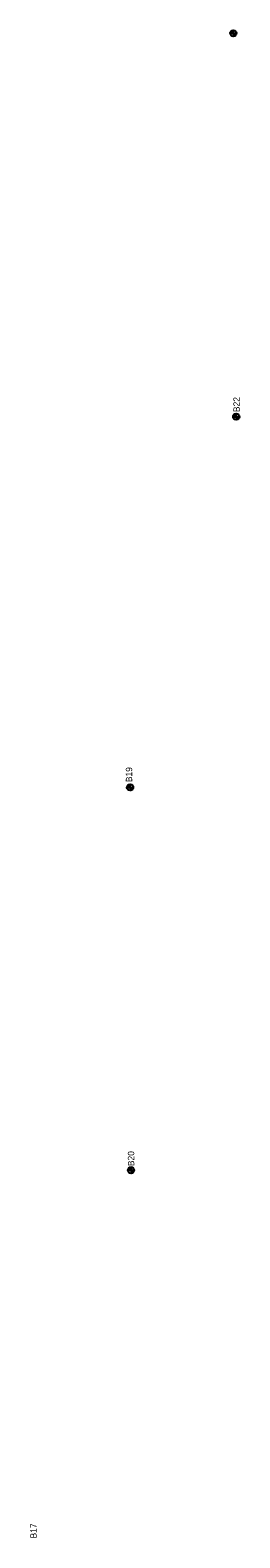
# Model space of a CAD drawing. Extents: x 327762 to 372792, y 127949 to 259367.
# Drawn here: x 361138 to 361467, y 137976 to 140354 of the extents above; entities that cross this region are included whole.
import ezdxf

# ---------------------------------------------------------------- set-up
doc = ezdxf.new("R2010")
doc.units = 0
for name, color, linetype in [('E_SOIL_BORE1 [KAPUR_CADDS_LEVELS]', 7, 'Continuous'), ('E_SOIL_BORE2 [KAPUR_CADDS_LEVELS]', 7, 'Continuous'), ('P_MARK', 7, 'Continuous')]:
    doc.layers.add(name, color=color, linetype=linetype)

msp = doc.modelspace()

# ---------------------------------------------------------------- linework, layer by layer
at = {"layer": 'P_MARK'}
for p, q in [((361452.1, 140348.7), (361462, 140348.7)), ((361457.1, 140353.7), (361457, 140343.7)), ((361456.7, 139744.2), (361466.7, 139744.2)), ((361461.7, 139749.2), (361461.7, 139739.2)), ((361289.9, 139159.7), (361299.9, 139159.7)), ((361294.9, 139164.7), (361294.9, 139154.7)), ((361291.3, 138556.1), (361301.3, 138556.1)), ((361296.3, 138561.1), (361296.3, 138551.1))]:
    msp.add_line(p, q, dxfattribs=at)
for centre in [(361457.1, 140348.7), (361461.7, 139744.2), (361294.9, 139159.7), (361296.3, 138556.1)]:
    msp.add_circle(centre, 5, dxfattribs=at)
for centre, radius, start, end in [((361457.1, 140348.7), 4.5, 89.9869, 179.9869), ((361457.1, 140348.7), 4, 89.9869, 179.9869), ((361457.1, 140348.7), 3.5, 89.9869, 179.9869), ((361457.1, 140348.7), 3, 89.9869, 179.9869), ((361457.1, 140348.7), 2.5, 89.9869, 179.9869), ((361457.1, 140348.7), 2, 89.9869, 179.9869), ((361457.1, 140348.7), 1.5, 89.9869, 179.9869), ((361457.1, 140348.7), 1, 89.9869, 179.9869), ((361457.1, 140348.7), 0.5, 89.9869, 179.9869), ((361457.1, 140348.7), 4.5, 269.9869, 359.9869), ((361457.1, 140348.7), 4, 269.9869, 359.9869), ((361457.1, 140348.7), 3.5, 269.9869, 359.9869), ((361457.1, 140348.7), 3, 269.9869, 359.9869), ((361457.1, 140348.7), 2.5, 269.9869, 359.9869), ((361457.1, 140348.7), 2, 269.9869, 359.9869), ((361457.1, 140348.7), 1.5, 269.9869, 359.9869), ((361457.1, 140348.7), 1, 269.9869, 359.9869), ((361457.1, 140348.7), 0.5, 269.9869, 359.9869), ((361461.7, 139744.2), 4.5, 89.9869, 179.9869), ((361461.7, 139744.2), 4, 89.9869, 179.9869), ((361461.7, 139744.2), 3.5, 89.9869, 179.9869), ((361461.7, 139744.2), 3, 89.9869, 179.9869), ((361461.7, 139744.2), 2.5, 89.9869, 179.9869), ((361461.7, 139744.2), 2, 89.9869, 179.9869), ((361461.7, 139744.2), 1.5, 89.9869, 179.9869), ((361461.7, 139744.2), 1, 89.9869, 179.9869), ((361461.7, 139744.2), 0.5, 89.9869, 179.9869), ((361461.7, 139744.2), 4.5, 269.9869, 359.9869), ((361461.7, 139744.2), 4, 269.9869, 359.9869), ((361461.7, 139744.2), 3.5, 269.9869, 359.9869), ((361461.7, 139744.2), 3, 269.9869, 359.9869), ((361461.7, 139744.2), 2.5, 269.9869, 359.9869), ((361461.7, 139744.2), 2, 269.9869, 359.9869), ((361461.7, 139744.2), 1.5, 269.9869, 359.9869), ((361461.7, 139744.2), 1, 269.9869, 359.9869), ((361461.7, 139744.2), 0.5, 269.9869, 359.9869), ((361294.9, 139159.7), 4.5, 89.9869, 179.9869), ((361294.9, 139159.7), 4, 89.9869, 179.9869), ((361294.9, 139159.7), 3.5, 89.9869, 179.9869), ((361294.9, 139159.7), 3, 89.9869, 179.9869), ((361294.9, 139159.7), 2.5, 89.9869, 179.9869), ((361294.9, 139159.7), 2, 89.9869, 179.9869), ((361294.9, 139159.7), 1.5, 89.9869, 179.9869), ((361294.9, 139159.7), 1, 89.9869, 179.9869), ((361294.9, 139159.7), 0.5, 89.9869, 179.9869), ((361294.9, 139159.7), 4.5, 269.9869, 359.9869), ((361294.9, 139159.7), 4, 269.9869, 359.9869), ((361294.9, 139159.7), 3.5, 269.9869, 359.9869), ((361294.9, 139159.7), 3, 269.9869, 359.9869), ((361294.9, 139159.7), 2.5, 269.9869, 359.9869), ((361294.9, 139159.7), 2, 269.9869, 359.9869), ((361294.9, 139159.7), 1.5, 269.9869, 359.9869), ((361294.9, 139159.7), 1, 269.9869, 359.9869), ((361294.9, 139159.7), 0.5, 269.9869, 359.9869), ((361296.3, 138556.1), 4.5, 89.9869, 179.9869), ((361296.3, 138556.1), 4, 89.9869, 179.9869), ((361296.3, 138556.1), 3.5, 89.9869, 179.9869), ((361296.3, 138556.1), 3, 89.9869, 179.9869), ((361296.3, 138556.1), 2.5, 89.9869, 179.9869), ((361296.3, 138556.1), 2, 89.9869, 179.9869), ((361296.3, 138556.1), 1.5, 89.9869, 179.9869), ((361296.3, 138556.1), 1, 89.9869, 179.9869), ((361296.3, 138556.1), 0.5, 89.9869, 179.9869), ((361296.3, 138556.1), 4.5, 269.9869, 359.9869), ((361296.3, 138556.1), 4, 269.9869, 359.9869), ((361296.3, 138556.1), 3.5, 269.9869, 359.9869), ((361296.3, 138556.1), 3, 269.9869, 359.9869), ((361296.3, 138556.1), 2.5, 269.9869, 359.9869), ((361296.3, 138556.1), 2, 269.9869, 359.9869), ((361296.3, 138556.1), 1.5, 269.9869, 359.9869), ((361296.3, 138556.1), 1, 269.9869, 359.9869), ((361296.3, 138556.1), 0.5, 269.9869, 359.9869)]:
    msp.add_arc(centre, radius, start, end, dxfattribs=at)

# ---------------------------------------------------------------- texts
at = {"layer": 'E_SOIL_BORE1 [KAPUR_CADDS_LEVELS]'}
for s, p in [('B20', (361301.3, 138562.4)), ('B17', (361147.9, 137975.3))]:
    msp.add_text(s, height=10, rotation=89.9869, dxfattribs=at).set_placement(p)
at = {"layer": 'E_SOIL_BORE2 [KAPUR_CADDS_LEVELS]'}
for s, p in [('B22', (361467.2, 139751.4)), ('B19', (361298.1, 139167.9))]:
    msp.add_text(s, height=10, rotation=89.9869, dxfattribs=at).set_placement(p)

doc.saveas('drawing.dxf')
